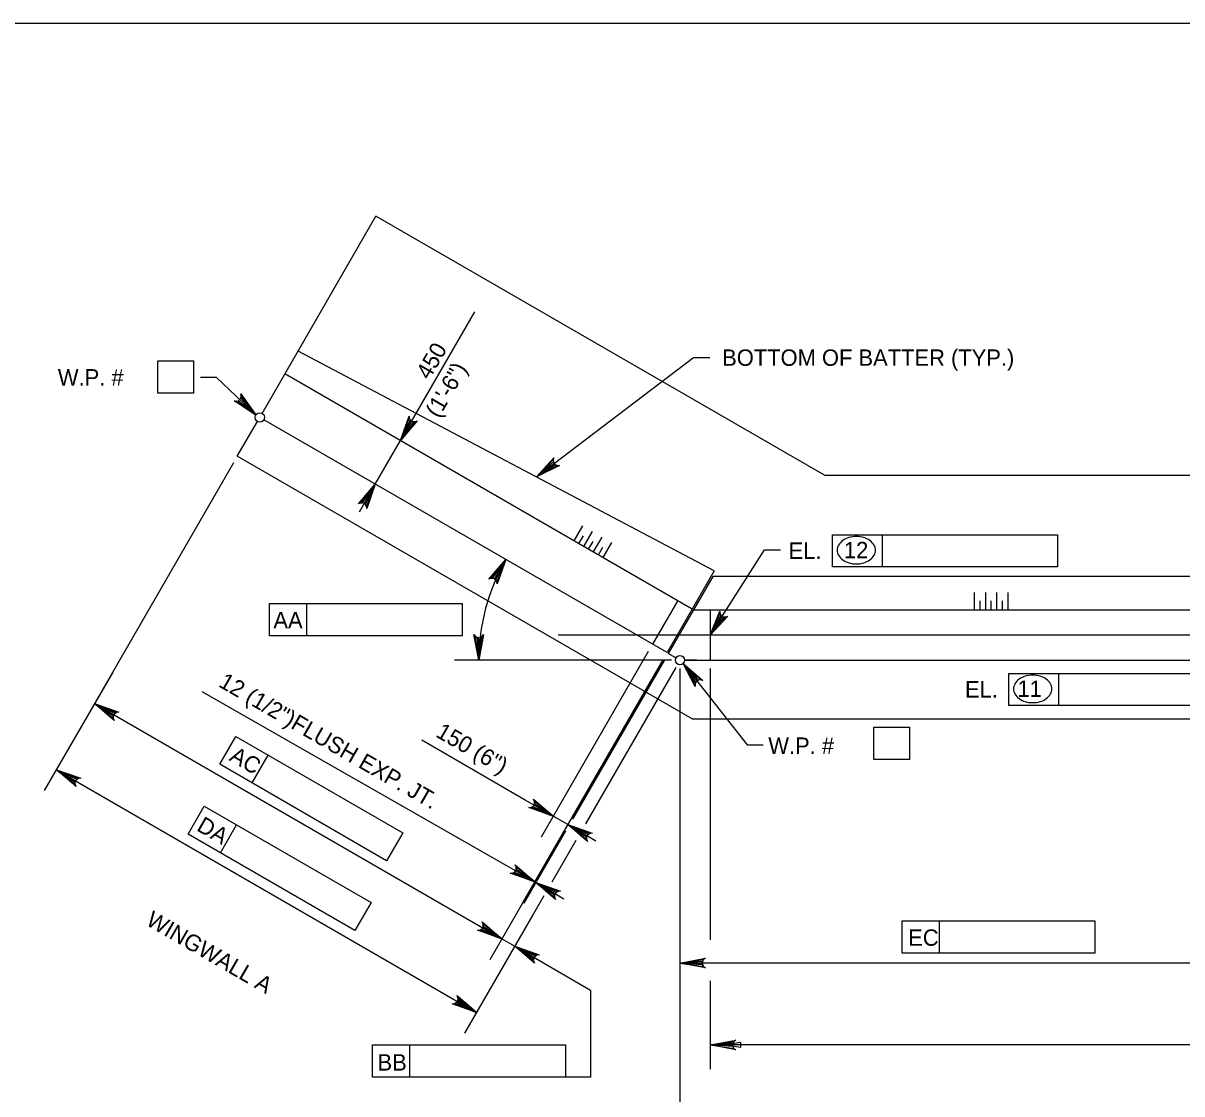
# Model space of a CAD drawing. Extents: x 634540 to 640306, y 296059 to 300275.
# Drawn here: x 638496.3 to 638708.4, y 297630.5 to 297826.5 of the extents above; entities that cross this region are included whole.
import ezdxf

# ---------------------------------------------------------------- set-up
doc = ezdxf.new("R2010")
doc.units = 0
for name, color, linetype in [('10', 7, 'Continuous'), ('2', 7, 'Continuous'), ('3', 7, 'Continuous')]:
    doc.layers.add(name, color=color, linetype=linetype)

msp = doc.modelspace()

# ---------------------------------------------------------------- linework, layer by layer
at = {"layer": '10'}
for p, q in [((638540.01, 297755.02), (638560.86, 297791.13)), ((638643.03, 297743.69), (638560.86, 297791.13)), ((638622.82, 297726.2), (638546.6, 297766.44)), ((638618.78, 297719.21), (638544.2, 297762.27)), ((638535.48, 297747.18), (638539.16, 297753.54)), ((638614.17, 297711.22), (638540.32, 297753.86)), ((638618.78, 297699.09), (638535.48, 297747.18)), ((638643.03, 297743.69), (638817.28, 297743.69)), ((638622.82, 297726.2), (638614.17, 297711.22)), ((638622.53, 297725.18), (638614.39, 297711.09)), ((638838.7, 297725.11), (638622.53, 297725.18)), ((638616.12, 297720.75), (638611.51, 297712.76)), ((638619.01, 297719.08), (638842.18, 297719.08)), ((638622.08, 297719.08), (638622.08, 297709.85)), ((638594.25, 297714.47), (638859.46, 297714.47)), ((638615.8, 297710.28), (638614.39, 297711.09)), ((638617.38, 297709.85), (638727.3, 297709.85)), ((638619.61, 297709.85), (638617.38, 297709.85)), ((638618.78, 297699.09), (638838.46, 297699.09))]:
    msp.add_line(p, q, dxfattribs=at)
at = {"layer": '2'}
for p, q in [((638475.46, 297826.46), (639261.46, 297826.46)), ((638597.15, 297731.7), (638598.73, 297734.44)), ((638598.04, 297731.19), (638598.85, 297732.6)), ((638598.92, 297730.68), (638600.5, 297733.41)), ((638600.7, 297729.65), (638602.28, 297732.39)), ((638599.81, 297730.17), (638600.62, 297731.57)), ((638601.59, 297729.14), (638602.4, 297730.55)), ((638602.47, 297728.63), (638604.05, 297731.36)), ((638670.46, 297719.08), (638670.46, 297722.24)), ((638672.51, 297719.08), (638672.51, 297722.24)), ((638674.56, 297719.08), (638674.56, 297722.24)), ((638676.61, 297719.08), (638676.61, 297722.24)), ((638671.48, 297719.08), (638671.48, 297720.7)), ((638673.54, 297719.08), (638673.54, 297720.7)), ((638675.59, 297719.08), (638675.59, 297720.7))]:
    msp.add_line(p, q, dxfattribs=at)
at = {"layer": '3'}
for p, q in [((638565.36, 297750.06), (638578.97, 297773.61)), ((638520.95, 297758.71), (638520.95, 297764.62)), ((638520.95, 297764.62), (638527.55, 297764.62)), ((638527.55, 297758.71), (638527.55, 297764.62)), ((638590.26, 297743.39), (638619.01, 297765.24)), ((638619.01, 297765.24), (638622.01, 297765.24)), ((638531.7, 297761.59), (638528.75, 297761.59)), ((638538.87, 297754.73), (638531.7, 297761.59)), ((638527.55, 297758.71), (638520.95, 297758.71)), ((638560.74, 297742.07), (638565.36, 297750.06)), ((638534.8, 297745.99), (638507.13, 297698.06)), ((638560.74, 297742.07), (638557.79, 297736.95)), ((638644.45, 297732.81), (638653.62, 297732.81)), ((638644.45, 297726.91), (638644.45, 297732.81)), ((638653.62, 297726.91), (638653.62, 297732.81)), ((638653.62, 297732.81), (638685.66, 297732.81)), ((638685.66, 297732.81), (638685.66, 297726.91)), ((638622.05, 297714.43), (638632.02, 297730.02)), ((638632.02, 297730.02), (638634.97, 297730.02)), ((638685.66, 297726.91), (638644.45, 297726.91)), ((638541.36, 297720.23), (638548.21, 297720.23)), ((638541.36, 297714.33), (638541.36, 297720.23)), ((638548.21, 297714.33), (638548.21, 297720.23)), ((638548.21, 297720.23), (638576.67, 297720.23)), ((638576.67, 297720.23), (638576.67, 297714.33)), ((638576.67, 297714.33), (638541.36, 297714.33)), ((638610.74, 297711.42), (638591.12, 297677.45)), ((638615, 297709.85), (638575.27, 297709.85)), ((638613.4, 297709.89), (638581.71, 297655)), ((638613.4, 297709.89), (638587.73, 297665.42)), ((638613.4, 297709.89), (638593.79, 297675.91)), ((638613.62, 297709.76), (638596.86, 297680.72)), ((638615.77, 297708.52), (638599.25, 297679.91)), ((638617.14, 297709.24), (638628.82, 297694.33)), ((638512.67, 297707.65), (638500.14, 297685.96)), ((638616.53, 297708.32), (638616.53, 297649.97)), ((638622.08, 297708.32), (638622.08, 297658.65)), ((638676.75, 297701.52), (638676.75, 297707.43)), ((638676.75, 297707.43), (638685.92, 297707.43)), ((638685.92, 297701.52), (638685.92, 297707.43)), ((638685.92, 297707.43), (638717.86, 297707.43)), ((638584.83, 297672.21), (638529.05, 297704.06)), ((638509.34, 297701.9), (638583.93, 297658.83)), ((638717.96, 297701.52), (638676.75, 297701.52)), ((638532.26, 297690.79), (638535.21, 297695.9)), ((638535.21, 297695.9), (638541.14, 297692.48)), ((638652.03, 297697.57), (638658.62, 297697.57)), ((638652.03, 297691.66), (638652.03, 297697.57)), ((638658.62, 297691.66), (638658.62, 297697.57)), ((638588.22, 297684.24), (638569.27, 297695.18)), ((638628.82, 297694.33), (638631.77, 297694.33)), ((638538.19, 297687.36), (638541.14, 297692.48)), ((638541.14, 297692.48), (638565.79, 297678.25)), ((638658.62, 297691.66), (638652.03, 297691.66)), ((638502.35, 297689.8), (638579.31, 297645.37)), ((638562.83, 297673.14), (638532.26, 297690.79)), ((638526.46, 297678.01), (638529.41, 297683.12)), ((638529.41, 297683.12), (638535.34, 297679.7)), ((638590.78, 297682.76), (638588.22, 297684.24)), ((638596, 297679.75), (638593.34, 297681.28)), ((638532.39, 297674.58), (638535.34, 297679.7)), ((638535.34, 297679.7), (638559.98, 297665.47)), ((638557.03, 297660.36), (638526.46, 297678.01)), ((638565.79, 297678.25), (638562.83, 297673.14)), ((638595.59, 297678.53), (638587.95, 297665.29)), ((638597.46, 297676.81), (638593.06, 297669.19)), ((638598.56, 297678.27), (638601.12, 297676.79)), ((638587.39, 297670.73), (638584.83, 297672.21)), ((638590.17, 297669.13), (638589.95, 297669.26)), ((638616.53, 297669.3), (638616.53, 297620.56)), ((638591.62, 297666.7), (638584.08, 297653.63)), ((638592.73, 297667.66), (638595.28, 297666.18)), ((638559.98, 297665.47), (638557.03, 297660.36)), ((638589.61, 297663.23), (638577.09, 297641.54)), ((638581.37, 297660.31), (638578.81, 297661.79)), ((638657.21, 297662.13), (638664.06, 297662.13)), ((638657.21, 297656.23), (638657.21, 297662.13)), ((638664.06, 297656.23), (638664.06, 297662.13)), ((638664.06, 297662.13), (638692.51, 297662.13)), ((638692.51, 297662.13), (638692.51, 297656.23)), ((638583.93, 297658.83), (638586.29, 297657.47)), ((638586.29, 297657.47), (638600.16, 297649.46)), ((638588.85, 297655.99), (638591.4, 297654.51)), ((638692.51, 297656.23), (638657.21, 297656.23)), ((638730.24, 297654.4), (638616.53, 297654.4)), ((638622.08, 297651.17), (638622.08, 297634.98)), ((638600.16, 297649.46), (638600.16, 297633.51)), ((638560.25, 297639.41), (638567.1, 297639.41)), ((638560.25, 297633.51), (638560.25, 297639.41)), ((638567.1, 297633.51), (638567.1, 297639.41)), ((638567.1, 297639.41), (638595.56, 297639.41)), ((638595.56, 297639.41), (638595.56, 297633.51)), ((638839.1, 297639.41), (638624.65, 297639.41)), ((638595.56, 297633.51), (638560.25, 297633.51)), ((638600.16, 297633.51), (638595.56, 297633.51))]:
    msp.add_line(p, q, dxfattribs=at)
for points in [[(638538.87, 297754.73), (638534.9, 297757.32), (638535.33, 297757.26), (638535.68, 297757.35), (638535.93, 297757.54), (638536.11, 297757.81), (638536.19, 297758.16), (638536.1, 297758.59), (638538.87, 297754.73), (638536.19, 297758.16), (638536.11, 297757.81), (638538.87, 297754.73), (638535.93, 297757.54), (638535.68, 297757.35), (638538.87, 297754.73), (638535.33, 297757.26)], [(638565.36, 297750.06), (638566.93, 297754.53), (638566.97, 297754.1), (638567.14, 297753.78), (638567.39, 297753.58), (638567.69, 297753.47), (638568.05, 297753.47), (638568.44, 297753.66), (638565.36, 297750.06), (638568.05, 297753.47), (638567.69, 297753.47), (638565.36, 297750.06), (638567.39, 297753.58), (638567.14, 297753.78), (638565.36, 297750.06), (638566.97, 297754.1)], [(638590.26, 297743.39), (638593.44, 297746.9), (638593.3, 297746.49), (638593.35, 297746.13), (638593.49, 297745.85), (638593.73, 297745.63), (638594.06, 297745.49), (638594.5, 297745.51), (638590.26, 297743.39), (638594.06, 297745.49), (638593.73, 297745.63), (638590.26, 297743.39), (638593.49, 297745.85), (638593.35, 297746.13), (638590.26, 297743.39), (638593.3, 297746.49)], [(638560.74, 297742.07), (638559.17, 297737.59), (638559.13, 297738.03), (638558.95, 297738.35), (638558.71, 297738.55), (638558.41, 297738.66), (638558.05, 297738.65), (638557.65, 297738.47), (638560.74, 297742.07), (638558.05, 297738.65), (638558.41, 297738.66), (638560.74, 297742.07), (638558.71, 297738.55), (638558.95, 297738.35), (638560.74, 297742.07), (638559.13, 297738.03)], [(638584.63, 297728.27), (638583.06, 297723.8), (638583.02, 297724.24), (638582.85, 297724.55), (638582.6, 297724.76), (638582.3, 297724.87), (638581.94, 297724.86), (638581.55, 297724.67), (638584.63, 297728.27), (638581.94, 297724.86), (638582.3, 297724.87), (638584.63, 297728.27), (638582.6, 297724.76), (638582.85, 297724.55), (638584.63, 297728.27), (638583.02, 297724.24)], [(638622.05, 297714.43), (638623.82, 297718.83), (638623.84, 297718.39), (638624.01, 297718.07), (638624.24, 297717.85), (638624.53, 297717.73), (638624.9, 297717.72), (638625.3, 297717.88), (638622.05, 297714.43), (638624.9, 297717.72), (638624.53, 297717.73), (638622.05, 297714.43), (638624.24, 297717.85), (638624.01, 297718.07), (638622.05, 297714.43), (638623.84, 297718.39)], [(638579.7, 297709.85), (638578.82, 297714.52), (638579.07, 297714.16), (638579.39, 297713.97), (638579.7, 297713.92), (638580.01, 297713.97), (638580.32, 297714.16), (638580.57, 297714.52), (638579.7, 297709.85), (638580.32, 297714.16), (638580.01, 297713.97), (638579.7, 297709.85), (638579.7, 297713.92), (638579.39, 297713.97), (638579.7, 297709.85), (638579.07, 297714.16)], [(638617.14, 297709.24), (638620.7, 297706.11), (638620.28, 297706.24), (638619.92, 297706.2), (638619.65, 297706.05), (638619.43, 297705.81), (638619.3, 297705.47), (638619.33, 297705.04), (638617.14, 297709.24), (638619.3, 297705.47), (638619.43, 297705.81), (638617.14, 297709.24), (638619.65, 297706.05), (638619.92, 297706.2), (638617.14, 297709.24), (638620.28, 297706.24)], [(638509.34, 297701.9), (638513.81, 297700.32), (638513.38, 297700.29), (638513.06, 297700.11), (638512.86, 297699.86), (638512.75, 297699.57), (638512.75, 297699.2), (638512.94, 297698.81), (638509.34, 297701.9), (638512.75, 297699.2), (638512.75, 297699.57), (638509.34, 297701.9), (638512.86, 297699.86), (638513.06, 297700.11), (638509.34, 297701.9), (638513.38, 297700.29)], [(638502.35, 297689.8), (638506.83, 297688.22), (638506.39, 297688.19), (638506.08, 297688.01), (638505.87, 297687.77), (638505.76, 297687.47), (638505.77, 297687.11), (638505.95, 297686.71), (638502.35, 297689.8), (638505.77, 297687.11), (638505.76, 297687.47), (638502.35, 297689.8), (638505.87, 297687.77), (638506.08, 297688.01), (638502.35, 297689.8), (638506.39, 297688.19)], [(638593.34, 297681.28), (638588.86, 297682.86), (638589.3, 297682.89), (638589.61, 297683.07), (638589.82, 297683.31), (638589.93, 297683.61), (638589.92, 297683.97), (638589.74, 297684.37), (638593.34, 297681.28), (638589.92, 297683.97), (638589.93, 297683.61), (638593.34, 297681.28), (638589.82, 297683.31), (638589.61, 297683.07), (638593.34, 297681.28), (638589.3, 297682.89)], [(638596, 297679.75), (638600.47, 297678.17), (638600.04, 297678.14), (638599.72, 297677.96), (638599.52, 297677.71), (638599.41, 297677.42), (638599.41, 297677.05), (638599.6, 297676.66), (638596, 297679.75), (638599.41, 297677.05), (638599.41, 297677.42), (638596, 297679.75), (638599.52, 297677.71), (638599.72, 297677.96), (638596, 297679.75), (638600.04, 297678.14)], [(638589.95, 297669.26), (638585.47, 297670.83), (638585.91, 297670.87), (638586.22, 297671.05), (638586.43, 297671.29), (638586.54, 297671.59), (638586.53, 297671.95), (638586.35, 297672.35), (638589.95, 297669.26), (638586.53, 297671.95), (638586.54, 297671.59), (638589.95, 297669.26), (638586.43, 297671.29), (638586.22, 297671.05), (638589.95, 297669.26), (638585.91, 297670.87)], [(638590.17, 297669.13), (638594.64, 297667.56), (638594.21, 297667.52), (638593.89, 297667.34), (638593.69, 297667.1), (638593.58, 297666.8), (638593.58, 297666.44), (638593.77, 297666.04), (638590.17, 297669.13), (638593.58, 297666.44), (638593.58, 297666.8), (638590.17, 297669.13), (638593.69, 297667.1), (638593.89, 297667.34), (638590.17, 297669.13), (638594.21, 297667.52)], [(638583.93, 297658.83), (638579.45, 297660.4), (638579.89, 297660.44), (638580.21, 297660.62), (638580.41, 297660.86), (638580.52, 297661.16), (638580.51, 297661.52), (638580.33, 297661.92), (638583.93, 297658.83), (638580.51, 297661.52), (638580.52, 297661.16), (638583.93, 297658.83), (638580.41, 297660.86), (638580.21, 297660.62), (638583.93, 297658.83), (638579.89, 297660.44)], [(638586.29, 297657.47), (638590.76, 297655.89), (638590.33, 297655.86), (638590.01, 297655.68), (638589.81, 297655.44), (638589.7, 297655.14), (638589.7, 297654.78), (638589.89, 297654.38), (638586.29, 297657.47), (638589.7, 297654.78), (638589.7, 297655.14), (638586.29, 297657.47), (638589.81, 297655.44), (638590.01, 297655.68), (638586.29, 297657.47), (638590.33, 297655.86)], [(638616.53, 297654.4), (638621.2, 297655.27), (638620.84, 297655.03), (638620.65, 297654.71), (638620.6, 297654.4), (638620.65, 297654.09), (638620.84, 297653.78), (638621.2, 297653.53), (638616.53, 297654.4), (638620.84, 297653.78), (638620.65, 297654.09), (638616.53, 297654.4), (638620.6, 297654.4), (638620.65, 297654.71), (638616.53, 297654.4), (638620.84, 297655.03)], [(638579.31, 297645.37), (638574.83, 297646.94), (638575.27, 297646.98), (638575.58, 297647.16), (638575.79, 297647.4), (638575.9, 297647.7), (638575.89, 297648.06), (638575.71, 297648.46), (638579.31, 297645.37), (638575.89, 297648.06), (638575.9, 297647.7), (638579.31, 297645.37), (638575.79, 297647.4), (638575.58, 297647.16), (638579.31, 297645.37), (638575.27, 297646.98)], [(638622.08, 297639.41), (638626.74, 297640.28), (638626.39, 297640.03), (638626.2, 297639.72), (638626.15, 297639.41), (638626.2, 297639.1), (638626.39, 297638.78), (638626.74, 297638.53), (638622.08, 297639.41), (638626.39, 297638.78), (638626.2, 297639.1), (638622.08, 297639.41), (638626.15, 297639.41), (638626.2, 297639.72), (638622.08, 297639.41), (638626.39, 297640.03)]]:
    msp.add_lwpolyline(points, dxfattribs=at)
for points in [[(638537.07, 297757.13), (638536.39, 297756.42), (638538.86, 297754.73)], [(638566.41, 297752.86), (638567.26, 297752.37), (638565.36, 297750.06)], [(638593.16, 297744.96), (638592.55, 297745.76), (638590.46, 297743.55)], [(638558.84, 297739.75), (638559.69, 297739.26), (638560.74, 297742.07)], [(638582.82, 297725.89), (638583.7, 297725.43), (638584.63, 297728.27)], [(638580.31, 297712.78), (638579.32, 297712.82), (638579.7, 297709.85)], [(638618.57, 297706.62), (638619.34, 297707.23), (638617.14, 297709.25)], [(638512.14, 297700.85), (638511.65, 297699.99), (638509.34, 297701.9)], [(638505.16, 297688.75), (638504.67, 297687.9), (638502.35, 297689.8)], [(638591.03, 297683.18), (638590.53, 297682.33), (638593.34, 297681.28)], [(638598.8, 297678.7), (638598.31, 297677.84), (638596, 297679.75)], [(638587.64, 297671.16), (638587.14, 297670.31), (638589.95, 297669.26)], [(638592.97, 297668.08), (638592.48, 297667.23), (638590.17, 297669.13)], [(638581.62, 297660.74), (638581.12, 297659.88), (638583.93, 297658.83)], [(638589.09, 297656.42), (638588.6, 297655.56), (638586.29, 297657.47)], [(638619.49, 297654.89), (638619.49, 297653.91), (638616.53, 297654.4)], [(638577, 297647.27), (638576.5, 297646.42), (638579.31, 297645.37)], [(638627.61, 297639.9), (638627.61, 297638.92), (638624.65, 297639.41)]]:
    msp.add_lwpolyline(points, close=True, dxfattribs=at)
for centre in [(638539.59, 297754.28), (638616.54, 297709.85)]:
    msp.add_circle(centre, 0.85, dxfattribs=at)
for centre, radius, start, end in [((638648.48, 297728.77), 3.66, 106.5358, 125.6316), ((638648.82, 297727.61), 4.87, 90, 106.5358), ((638648.82, 297727.61), 4.87, 73.4642, 90), ((638649.17, 297728.77), 3.66, 54.3684, 73.4642), ((638647.15, 297729.97), 1.83, 149.9767, 180), ((638647.15, 297729.97), 1.83, 180, 210.0233), ((638647.95, 297729.5), 2.76, 125.6316, 149.9767), ((638649.7, 297729.5), 2.76, 30.0233, 54.3684), ((638650.5, 297729.97), 1.83, 0, 30.0233), ((638650.5, 297729.97), 1.83, 329.9767, 0), ((638616.54, 297709.85), 36.84, 149.9988, 180), ((638647.95, 297730.43), 2.76, 210.0233, 234.3684), ((638648.48, 297731.17), 3.66, 234.3684, 253.4642), ((638648.82, 297732.33), 4.87, 253.4642, 270), ((638648.82, 297732.33), 4.87, 270, 286.5358), ((638649.17, 297731.17), 3.66, 286.5358, 305.6316), ((638649.7, 297730.43), 2.76, 305.6316, 329.9767), ((638616.54, 297709.85), 36.84, 174.95, 175.4061), ((638680.25, 297704.12), 2.76, 125.6316, 149.9767), ((638680.78, 297703.38), 3.66, 106.5358, 125.6316), ((638681.12, 297702.22), 4.87, 90, 106.5358), ((638681.12, 297702.22), 4.87, 73.4642, 90), ((638681.47, 297703.38), 3.66, 54.3684, 73.4642), ((638682, 297704.12), 2.76, 30.0233, 54.3684), ((638679.45, 297704.58), 1.83, 149.9767, 180), ((638679.45, 297704.58), 1.83, 180, 210.0233), ((638682.8, 297704.58), 1.83, 0, 30.0233), ((638682.8, 297704.58), 1.83, 329.9767, 0), ((638680.25, 297705.05), 2.76, 210.0233, 234.3684), ((638680.78, 297705.78), 3.66, 234.3684, 253.4642), ((638681.12, 297706.94), 4.87, 253.4642, 270), ((638681.12, 297706.94), 4.87, 270, 286.5358), ((638681.47, 297705.78), 3.66, 286.5358, 305.6316), ((638682, 297705.05), 2.76, 305.6316, 329.9767)]:
    msp.add_arc(centre, radius, start, end, dxfattribs=at)

# ---------------------------------------------------------------- texts
for s, height, rotation, p in [('450', 3, 60, (638570.65, 297761.02)), ('(1\'-6")', 3, 60, (638572.37, 297754.01)), ('12 (1/2")FLUSH EXP. JT.', 3.0001, 330, (638531.88, 297705.11)), ('150 (6")', 3, 330, (638571.63, 297695.94)), ('AC', 3, 330, (638533.83, 297691.58)), ('DA', 3, 330.0005, (638527.85, 297678.77)), ('WINGWALL A', 3, 330.0005, (638518.55, 297661.49))]:
    msp.add_text(s, height=height, rotation=rotation, dxfattribs=at).set_placement(p)
for s, height, p in [('BOTTOM OF BATTER (TYP.)', 3.0001, (638624.26, 297763.73)), ('W.P. # ', 3, (638502.63, 297760.12)), ('EL.', 3, (638636.43, 297728.39)), ('12', 3, (638646.55, 297728.5)), ('AA', 3, (638542.09, 297715.67)), ('EL.', 3, (638668.73, 297703.01)), ('11', 3, (638678.33, 297703.12)), ('W.P. # ', 3, (638632.71, 297692.69)), ('EC', 3, (638658.33, 297657.56)), ('BB', 3, (638561.16, 297634.71))]:
    msp.add_text(s, height=height, dxfattribs=at).set_placement(p)

doc.saveas('drawing.dxf')
